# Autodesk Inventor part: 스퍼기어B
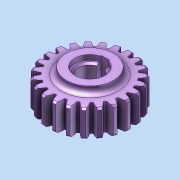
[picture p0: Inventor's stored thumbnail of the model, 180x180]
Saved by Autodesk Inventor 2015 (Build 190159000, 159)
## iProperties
Created: 2024-05
Part Number: 스퍼기어B
Material: 일반
Document SubType Name: Modeling
Designer: Administrator
Density: 1 g/cm^3
Appearance: 기본값
Author: Administrator
Author: jhkim
Creation Date: 2024-05-10
Sending System: Autodesk Inventor 2025
Preprocessor: ST-DEVELOPER v20
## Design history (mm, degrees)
node "스퍼기어B1"
node "솔리드1"
node "기준1"
